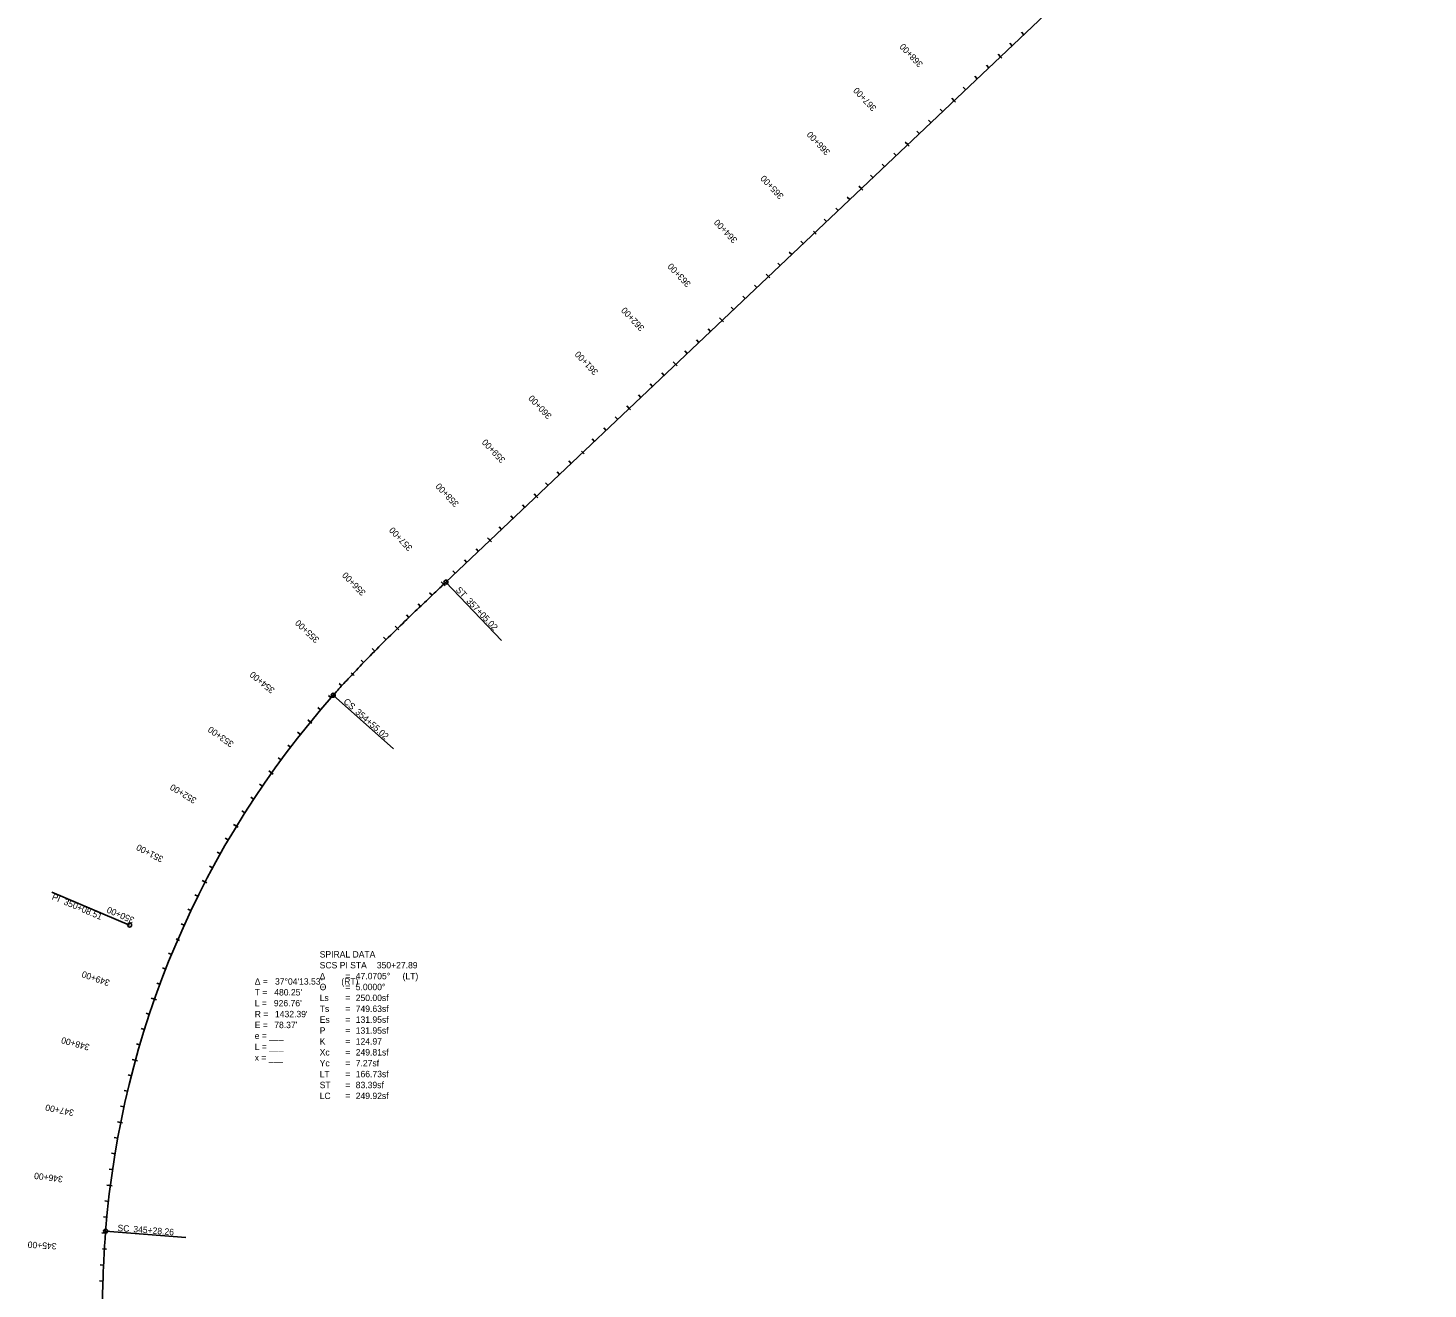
# Model space of a CAD drawing. Extents: x 23417911 to 23421158, y 6737892 to 6791804.
# Drawn here: x 23418107 to 23420297, y 6760918 to 6762891 of the extents above; entities that cross this region are included whole.
import ezdxf

# ---------------------------------------------------------------- set-up
doc = ezdxf.new("R2010")
doc.units = 0
for name, color, linetype in [('Alignment', 7, 'Continuous'), ('TextAlignment', 7, 'Continuous'), ('TextAlignmentLrg', 7, 'Continuous'), ('TextAlignmentSml', 7, 'Continuous')]:
    doc.layers.add(name, color=color, linetype=linetype)

msp = doc.modelspace()

# ---------------------------------------------------------------- linework, layer by layer
at = {"layer": 'Alignment'}
for q in [(23420297.1, 6763479.8), (23420296.2, 6763479), (23420296.2, 6763479)]:
    msp.add_line((23418761.1, 6762024.4), q, dxfattribs=at)
msp.add_arc((23419656.8, 6760897.4), 1432.4, 138.4569, 175.5274, dxfattribs=at)
msp.add_arc((23419656.8, 6760897.4), 1432.4, 138.4569, 175.5274, dxfattribs=at)
for points in [[(23418584.8, 6761847.3), (23418589.4, 6761852.5), (23418598.6, 6761862.8), (23418617.5, 6761883.2), (23418641.5, 6761908.3), (23418670.9, 6761937.8), (23418700.7, 6761966.9), (23418725.8, 6761990.9), (23418746, 6762010.1), (23418756, 6762019.6), (23418761.1, 6762024.4)], [(23418584.8, 6761847.3), (23418589.4, 6761852.5), (23418598.6, 6761862.8), (23418617.5, 6761883.2), (23418641.5, 6761908.3), (23418670.9, 6761937.8), (23418700.7, 6761966.9), (23418725.8, 6761990.9), (23418746, 6762010.1), (23418756, 6762019.6), (23418761.1, 6762024.4)], [(23418223.8, 6760759.2), (23418223.8, 6760766.2), (23418223.6, 6760780), (23418223.4, 6760807.8), (23418223.3, 6760842.5), (23418223.5, 6760884.2), (23418224.3, 6760925.9), (23418225.7, 6760960.6), (23418227.3, 6760988.3), (23418228.3, 6761002.2), (23418228.8, 6761009.1)], [(23418223.8, 6760759.2), (23418223.8, 6760766.2), (23418223.6, 6760780), (23418223.4, 6760807.8), (23418223.3, 6760842.5), (23418223.5, 6760884.2), (23418224.3, 6760925.9), (23418225.7, 6760960.6), (23418227.3, 6760988.3), (23418228.3, 6761002.2), (23418228.8, 6761009.1)]]:
    msp.add_open_spline(points, degree=3, dxfattribs=at)
at = {"layer": 'TextAlignment'}
for p, q in [((23418761.1, 6762024.4), (23418847.8, 6761932.9)), ((23418847.8, 6761932.9), (23418847.8, 6761932.9)), ((23418584.8, 6761847.3), (23418679.1, 6761763.7)), ((23418584.8, 6761847.3), (23418679.1, 6761763.7)), ((23418679.1, 6761763.7), (23418679.1, 6761763.7)), ((23418679.1, 6761763.7), (23418679.1, 6761763.7)), ((23418266.3, 6761487.9), (23418144.8, 6761539.5)), ((23418144.8, 6761539.5), (23418144.8, 6761539.5)), ((23418228.8, 6761009.1), (23418354.4, 6760999.2)), ((23418228.8, 6761009.1), (23418354.4, 6760999.2)), ((23418354.4, 6760999.2), (23418354.4, 6760999.2)), ((23418354.4, 6760999.2), (23418354.4, 6760999.2))]:
    msp.add_line(p, q, dxfattribs=at)
for centre in [(23418761.1, 6762024.4), (23418584.8, 6761847.3), (23418584.8, 6761847.3), (23418266.3, 6761487.9), (23418228.8, 6761009.1), (23418228.8, 6761009.1)]:
    msp.add_circle(centre, 3.12, dxfattribs=at)
at = {"layer": 'TextAlignmentLrg'}
for p, q in [((23419628.5, 6762846.3), (23419624.8, 6762850.3)), ((23419555.9, 6762777.5), (23419552.2, 6762781.5)), ((23419483.3, 6762708.8), (23419479.6, 6762712.7)), ((23419410.8, 6762640), (23419407, 6762643.9)), ((23419336.1, 6762573.4), (23419340.3, 6762569)), ((23419265.6, 6762502.4), (23419261.8, 6762506.4)), ((23419193, 6762433.6), (23419189.2, 6762437.6)), ((23419120.4, 6762364.9), (23419116.6, 6762368.8)), ((23419047.8, 6762296.1), (23419044, 6762300)), ((23418973.1, 6762229.5), (23418977.3, 6762225.1)), ((23418902.6, 6762158.5), (23418898.9, 6762162.5)), ((23418830, 6762089.7), (23418826.3, 6762093.7)), ((23418757.4, 6762021), (23418753.7, 6762024.9)), ((23418685.2, 6761951.8), (23418681.4, 6761955.7)), ((23418612.8, 6761882.6), (23418617.3, 6761878.4)), ((23418549.1, 6761805.4), (23418544.8, 6761808.9)), ((23418488.4, 6761726), (23418484, 6761729.1)), ((23418433.5, 6761642.4), (23418428.8, 6761645.3)), ((23418384.5, 6761555.3), (23418379.6, 6761557.8)), ((23418338.9, 6761466.1), (23418344.5, 6761463.7)), ((23418305.3, 6761371.8), (23418300.1, 6761373.6)), ((23418275.5, 6761276.4), (23418270.2, 6761277.8)), ((23418252.4, 6761179.1), (23418247.1, 6761180.2)), ((23418236.2, 6761080.4), (23418230.8, 6761081.1)), ((23418223.8, 6760981.1), (23418229.9, 6760980.7))]:
    msp.add_line(p, q, dxfattribs=at)
at = {"layer": 'TextAlignmentSml'}
for p, q in [((23419664.8, 6762880.7), (23419661.1, 6762884.7)), ((23419646.7, 6762863.5), (23419642.9, 6762867.5)), ((23419610.4, 6762829.1), (23419606.6, 6762833.1)), ((23419626.4, 6762848.5), (23419630.6, 6762844.1)), ((23419592.2, 6762811.9), (23419588.5, 6762815.9)), ((23419574.1, 6762794.7), (23419570.3, 6762798.7)), ((23419553.8, 6762779.8), (23419558, 6762775.3)), ((23419519.6, 6762743.2), (23419515.9, 6762747.1)), ((23419537.8, 6762760.4), (23419534, 6762764.3)), ((23419501.5, 6762726), (23419497.7, 6762729.9)), ((23419481.2, 6762711), (23419485.4, 6762706.5)), ((23419465.2, 6762691.6), (23419461.4, 6762695.5)), ((23419428.9, 6762657.2), (23419425.1, 6762661.1)), ((23419447, 6762674.4), (23419443.3, 6762678.3)), ((23419408.6, 6762642.2), (23419412.9, 6762637.8)), ((23419392.6, 6762622.8), (23419388.8, 6762626.8)), ((23419356.3, 6762588.4), (23419352.6, 6762592.4)), ((23419374.5, 6762605.6), (23419370.7, 6762609.6)), ((23419336.1, 6762573.4), (23419340.3, 6762569)), ((23419320, 6762554), (23419316.3, 6762558)), ((23419301.9, 6762536.8), (23419298.1, 6762540.8)), ((23419263.5, 6762504.6), (23419267.7, 6762500.2)), ((23419283.7, 6762519.6), (23419280, 6762523.6)), ((23419247.4, 6762485.2), (23419243.7, 6762489.2)), ((23419229.3, 6762468), (23419225.5, 6762472)), ((23419211.1, 6762450.8), (23419207.4, 6762454.8)), ((23419174.8, 6762416.4), (23419171.1, 6762420.4)), ((23419190.9, 6762435.9), (23419195.1, 6762431.4)), ((23419156.7, 6762399.3), (23419152.9, 6762403.2)), ((23419138.5, 6762382.1), (23419134.8, 6762386)), ((23419102.2, 6762347.7), (23419098.5, 6762351.6)), ((23419118.3, 6762367.1), (23419122.5, 6762362.6)), ((23419084.1, 6762330.5), (23419080.3, 6762334.4)), ((23419066, 6762313.3), (23419062.2, 6762317.2)), ((23419045.7, 6762298.3), (23419049.9, 6762293.9)), ((23419011.5, 6762261.7), (23419007.8, 6762265.7)), ((23419029.7, 6762278.9), (23419025.9, 6762282.8)), ((23418993.4, 6762244.5), (23418989.6, 6762248.5)), ((23418973.1, 6762229.5), (23418977.3, 6762225.1)), ((23418957.1, 6762210.1), (23418953.3, 6762214.1)), ((23418920.8, 6762175.7), (23418917, 6762179.7)), ((23418938.9, 6762192.9), (23418935.2, 6762196.9)), ((23418900.5, 6762160.7), (23418904.7, 6762156.3)), ((23418884.5, 6762141.3), (23418880.7, 6762145.3)), ((23418848.2, 6762106.9), (23418844.4, 6762110.9)), ((23418866.3, 6762124.1), (23418862.6, 6762128.1)), ((23418827.9, 6762092), (23418832.1, 6762087.5)), ((23418811.9, 6762072.5), (23418808.1, 6762076.5)), ((23418793.7, 6762055.3), (23418790, 6762059.3)), ((23418755.3, 6762023.2), (23418759.6, 6762018.7)), ((23418775.6, 6762038.2), (23418771.8, 6762042.1)), ((23418739.3, 6762003.8), (23418735.5, 6762007.7)), ((23418721.2, 6761986.5), (23418717.4, 6761990.5)), ((23418703.2, 6761969.2), (23418699.4, 6761973.1)), ((23418667.4, 6761934.2), (23418663.6, 6761938.1)), ((23418683.1, 6761954), (23418687.4, 6761949.6)), ((23418649.8, 6761916.5), (23418645.9, 6761920.4)), ((23418632.3, 6761898.6), (23418628.4, 6761902.4)), ((23418612.8, 6761882.6), (23418617.3, 6761878.4)), ((23418598.1, 6761862.2), (23418594.1, 6761865.9)), ((23418565.1, 6761824.6), (23418560.9, 6761828.2)), ((23418581.4, 6761843.5), (23418577.3, 6761847.2)), ((23418546.7, 6761807.4), (23418551.4, 6761803.5)), ((23418533.4, 6761786), (23418529.1, 6761789.4)), ((23418518.1, 6761766.2), (23418513.7, 6761769.5)), ((23418503.1, 6761746.2), (23418498.7, 6761749.5)), ((23418485.9, 6761727.7), (23418490.9, 6761724.2)), ((23418474.1, 6761705.4), (23418469.6, 6761708.5)), ((23418460.2, 6761684.7), (23418455.7, 6761687.7)), ((23418446.7, 6761663.7), (23418442, 6761666.6)), ((23418430.9, 6761644), (23418436.1, 6761640.8)), ((23418420.7, 6761621), (23418415.9, 6761623.7)), ((23418408.2, 6761599.3), (23418403.5, 6761602)), ((23418396.2, 6761577.4), (23418391.3, 6761580)), ((23418381.8, 6761556.7), (23418387.2, 6761553.9)), ((23418373.2, 6761533), (23418368.3, 6761535.4)), ((23418362.3, 6761510.5), (23418357.4, 6761512.8)), ((23418351.8, 6761487.8), (23418346.8, 6761490)), ((23418338.9, 6761466.1), (23418344.5, 6761463.7)), ((23418332, 6761441.9), (23418326.9, 6761444)), ((23418322.7, 6761418.7), (23418317.6, 6761420.7)), ((23418313.8, 6761395.3), (23418308.7, 6761397.2)), ((23418302.4, 6761372.8), (23418308.2, 6761370.8)), ((23418297.2, 6761348.1), (23418292, 6761349.9)), ((23418289.6, 6761324.3), (23418284.3, 6761326)), ((23418282.3, 6761300.4), (23418277.1, 6761301.9)), ((23418272.5, 6761277.2), (23418278.4, 6761275.6)), ((23418269.1, 6761252.2), (23418263.8, 6761253.6)), ((23418263.1, 6761227.9), (23418257.8, 6761229.2)), ((23418257.6, 6761203.5), (23418252.2, 6761204.7)), ((23418249.4, 6761179.7), (23418255.4, 6761178.5)), ((23418247.7, 6761154.5), (23418242.3, 6761155.5)), ((23418243.4, 6761129.9), (23418238.1, 6761130.8)), ((23418239.6, 6761105.2), (23418234.2, 6761106)), ((23418233.2, 6761080.8), (23418239.2, 6761080)), ((23418233.2, 6761055.6), (23418227.8, 6761056.2)), ((23418230.7, 6761030.7), (23418225.2, 6761031.2)), ((23418228.6, 6761005.8), (23418223.1, 6761006.2)), ((23418223.8, 6760981.1), (23418229.9, 6760980.7)), ((23418225.6, 6760955.9), (23418220.1, 6760956.2)), ((23418224.6, 6760930.9), (23418219.2, 6760931.1))]:
    msp.add_line(p, q, dxfattribs=at)

# ---------------------------------------------------------------- texts
at = {"layer": 'TextAlignment'}
for s, rotation, p in [('ST', 313.4569, (23418775.7, 6762011.5)), ('357+05.02', 313.4569, (23418792.2, 6761994)), ('CS', 318.4569, (23418599.9, 6761836.2)), ('CS', 318.4569, (23418599.9, 6761836.2)), ('354+55.02', 318.4569, (23418618.4, 6761819.7)), ('354+55.02', 318.4569, (23418618.4, 6761819.7)), ('PI ', 336.9921, (23418143.8, 6761528.4)), ('350+08.51', 336.9921, (23418162.2, 6761520.6)), ('SC', 355.5274, (23418247.1, 6761009.3)), ('SC', 355.5274, (23418247.1, 6761009.3)), ('345+28.26', 355.5274, (23418271.8, 6761007.4)), ('345+28.26', 355.5274, (23418271.8, 6761007.4))]:
    msp.add_text(s, height=10.02, rotation=rotation, dxfattribs=at).set_placement(p)
for s, height, p in [('SPIRAL DATA', 10.02, (23418563.6, 6761437.1)), ('Δ', 10, (23418563.6, 6761403.1)), ('SCS PI STA ', 10.02, (23418563.6, 6761420.1)), ('= ', 10.02, (23418603.7, 6761403.1)), ('47.0705°', 10.02, (23418620, 6761403.1)), ('350+27.89', 10.02, (23418653, 6761420.1)), (' (LT)', 10.02, (23418689.5, 6761403.1)), ('Δ = ', 10.02, (23418462, 6761394.7)), ("480.25'", 10.02, (23418492.5, 6761377.7)), ('37°04\'13.53"', 10.02, (23418493.7, 6761394.7)), ('Θ ', 10.02, (23418563.6, 6761386)), (' (RT)', 10.02, (23418593.7, 6761394.7)), ('= ', 10.02, (23418603.7, 6761386)), ('5.0000°', 10.02, (23418620, 6761386)), ('T = ', 10.02, (23418462, 6761377.7)), ('L = ', 10.02, (23418462, 6761360.7)), ("926.76'", 10.02, (23418491.9, 6761360.7)), ('Ls', 10.02, (23418563.6, 6761369)), ('= ', 10.02, (23418603.7, 6761369)), ('250.00sf', 10.02, (23418620, 6761369)), ('R = ', 10.02, (23418462, 6761343.6)), ("1432.39'", 10.02, (23418493.7, 6761343.6)), ('Ts', 10.02, (23418563.6, 6761352)), ('Es', 10.02, (23418563.6, 6761334.9)), ('= ', 10.02, (23418603.7, 6761352)), ('749.63sf', 10.02, (23418620, 6761352)), ('131.95sf', 10.02, (23418620, 6761334.9)), ('E = ', 10.02, (23418462, 6761326.6)), ("78.37'", 10.02, (23418492.5, 6761326.6)), ('P', 10, (23418563.6, 6761317.9)), ('= ', 10.02, (23418603.7, 6761334.9)), ('= ', 10.02, (23418603.7, 6761317.9)), ('131.95sf', 10.02, (23418620, 6761317.9)), ('e = ___ ', 10.02, (23418462, 6761309.6)), ('L = ___', 10.02, (23418462, 6761292.5)), ('K', 10, (23418563.6, 6761300.9)), ('= ', 10.02, (23418603.7, 6761300.9)), ('124.97', 10.02, (23418620, 6761300.9)), ('x = ___', 10.02, (23418462, 6761275.5)), ('Xc', 10.02, (23418563.6, 6761283.8)), ('= ', 10.02, (23418603.7, 6761283.8)), ('249.81sf', 10.02, (23418620, 6761283.8)), ('Yc', 10.02, (23418563.6, 6761266.8)), ('LT', 10.02, (23418563.6, 6761249.8)), ('= ', 10.02, (23418603.7, 6761266.8)), ('= ', 10.02, (23418603.7, 6761249.8)), ('7.27sf', 10.02, (23418620, 6761266.8)), ('166.73sf', 10.02, (23418620, 6761249.8)), ('ST ', 10.02, (23418563.6, 6761232.7)), ('= ', 10.02, (23418603.7, 6761232.7)), ('83.39sf', 10.02, (23418620, 6761232.7)), ('LC', 10.02, (23418563.6, 6761215.7)), ('= ', 10.02, (23418603.7, 6761215.7)), ('249.92sf', 10.02, (23418620, 6761215.7))]:
    msp.add_text(s, height=height, dxfattribs=at).set_placement(p)
at = {"layer": 'TextAlignmentLrg'}
for s, rotation, p in [('365+00', 133.4569, (23419290.2, 6762629.1)), ('360+00', 133.4569, (23418927.3, 6762285.2)), ('355+00', 136.8194, (23418563.8, 6761935.5)), ('350+00', 156.6576, (23418274.8, 6761499.2)), ('345+00', 176.5938, (23418152.3, 6760990.3))]:
    msp.add_text(s, height=10.02, rotation=rotation, dxfattribs=at).set_placement(p)
at = {"layer": 'TextAlignmentSml'}
for s, rotation, p in [('368+00', 133.4569, (23419508, 6762835.4)), ('367+00', 133.4569, (23419435.4, 6762766.7)), ('366+00', 133.4569, (23419362.8, 6762697.9)), ('365+00', 133.4569, (23419290.2, 6762629.1)), ('364+00', 133.4569, (23419217.6, 6762560.3)), ('363+00', 133.4569, (23419145, 6762491.5)), ('362+00', 133.4569, (23419072.4, 6762422.7)), ('361+00', 133.4569, (23418999.9, 6762354)), ('360+00', 133.4569, (23418927.3, 6762285.2)), ('359+00', 133.4569, (23418854.7, 6762216.4)), ('358+00', 133.4569, (23418782.1, 6762147.6)), ('357+00', 133.4589, (23418709.5, 6762078.8)), ('356+00', 134.3392, (23418636.4, 6762008.9)), ('355+00', 136.8194, (23418563.8, 6761935.5)), ('354+00', 140.6576, (23418494.2, 6761856.9)), ('353+00', 144.6576, (23418430.1, 6761773.4)), ('352+00', 148.6576, (23418372, 6761685.7)), ('351+00', 152.6576, (23418320.2, 6761594.2)), ('350+00', 156.6576, (23418274.8, 6761499.2)), ('349+00', 160.6576, (23418236.2, 6761401.4)), ('348+00', 164.6576, (23418204.5, 6761301)), ('347+00', 168.6577, (23418179.9, 6761198.7)), ('346+00', 172.6577, (23418162.4, 6761095)), ('345+00', 176.5938, (23418152.3, 6760990.3))]:
    msp.add_text(s, height=10.02, rotation=rotation, dxfattribs=at).set_placement(p)

doc.saveas('drawing.dxf')
